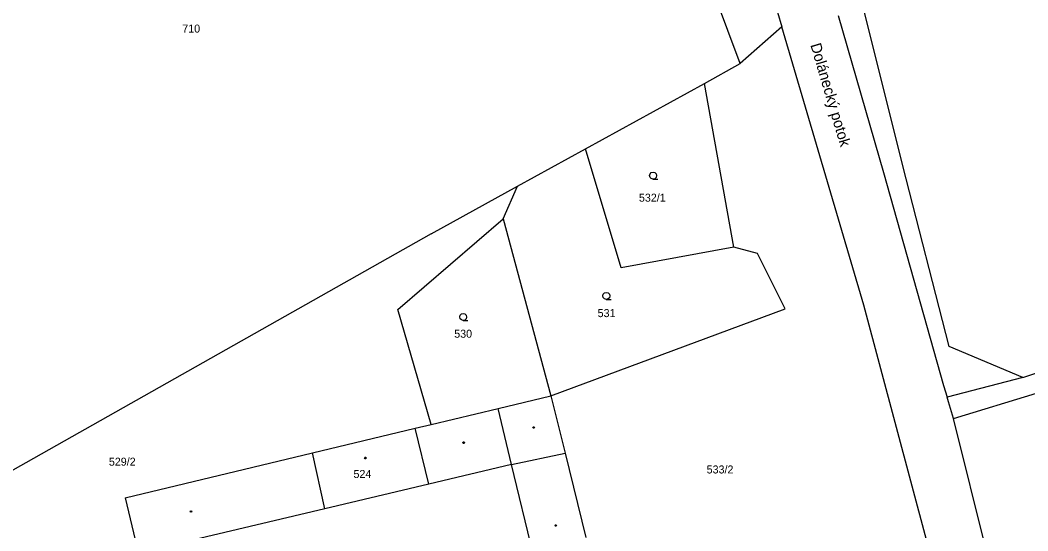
# Model space of a CAD drawing. Extents: x -812394 to -807601, y -1013097 to -1009266.
# Drawn here: x -809217.6 to -809003.5, y -1011595.7 to -1011487.2 of the extents above; entities that cross this region are included whole.
import ezdxf

# ---------------------------------------------------------------- set-up
doc = ezdxf.new("R2010")
doc.units = 0
for name, color, linetype in [('Default', 7, 'Continuous'), ('KN_HRANICE', 7, 'Continuous'), ('KN_KULTURY', 7, 'Continuous'), ('KN_PARCELY', 7, 'Continuous'), ('KN_SLUCKY', 7, 'Continuous')]:
    doc.layers.add(name, color=color, linetype=linetype)

# ---------------------------------------------------------------- blocks, each defined once
blk = doc.blocks.new('304')
at = {"layer": 'Default'}
blk.add_lwpolyline([(0, 0), (-0.38, 0.1), (-0.65, 0.37), (-0.75, 0.74), (-0.65, 1.11), (-0.38, 1.38), (-0.01, 1.48), (0.36, 1.38), (0.63, 1.11), (0.73, 0.73), (0.63, 0.35), (0.36, 0.08), (-0.02, -0.02), (0.98, -0.02)], dxfattribs=at)
blk = doc.blocks.new('402')
at = {"layer": 'Default'}
blk.add_lwpolyline([(0.09, 0.15), (0.18, 0), (0.09, -0.15), (-0.09, -0.15), (-0.18, 0), (-0.09, 0.15), (0.09, 0.15)], dxfattribs=at)

msp = doc.modelspace()

# ---------------------------------------------------------------- linework, layer by layer
at = {"layer": 'KN_HRANICE'}
for p, q in [((-809064.62, -1011496.45), (-809087.91, -1011433.54)), ((-809062.99, -1011464.38), (-809055.78, -1011488.65)), ((-809043.77, -1011486.23), (-809034.16, -1011519.56)), ((-809055.78, -1011488.65), (-809064.62, -1011496.45)), ((-809038.36, -1011547.76), (-809055.78, -1011488.65)), ((-809072.23, -1011500.64), (-809064.62, -1011496.45)), ((-809097.48, -1011514.55), (-809072.23, -1011500.64)), ((-809065.99, -1011535.45), (-809072.23, -1011500.64)), ((-809111.92, -1011522.51), (-809097.48, -1011514.55)), ((-809089.91, -1011539.85), (-809097.48, -1011514.55)), ((-809034.16, -1011519.56), (-809021.4, -1011564.8)), ((-809130.26, -1011532.62), (-809111.92, -1011522.51)), ((-809114.97, -1011529.38), (-809111.92, -1011522.51)), ((-809137.33, -1011548.69), (-809114.97, -1011529.38)), ((-809114.97, -1011529.38), (-809104.83, -1011566.99)), ((-809130.26, -1011532.62), (-809234.03, -1011591.15)), ((-809065.99, -1011535.45), (-809089.91, -1011539.85)), ((-809060.91, -1011536.79), (-809065.99, -1011535.45)), ((-809055.04, -1011548.54), (-809060.91, -1011536.79)), ((-809130.29, -1011573.09), (-809137.33, -1011548.69)), ((-809104.83, -1011566.99), (-809055.04, -1011548.54)), ((-809024.74, -1011598.61), (-809038.36, -1011547.76)), ((-809004.54, -1011563.13), (-808974.75, -1011553.11)), ((-809004.54, -1011563.13), (-809020.63, -1011567.3)), ((-809021.4, -1011564.8), (-809020.63, -1011567.3)), ((-809116.05, -1011569.68), (-809104.83, -1011566.99)), ((-809104.83, -1011566.99), (-809101.83, -1011579.14)), ((-809019.32, -1011571.78), (-809001.64, -1011566.41)), ((-809130.29, -1011573.09), (-809116.05, -1011569.68)), ((-809007.85, -1011617.52), (-809019.32, -1011571.78)), ((-809155.46, -1011579.11), (-809133.63, -1011573.89)), ((-809133.63, -1011573.89), (-809130.29, -1011573.09)), ((-809195.25, -1011588.63), (-809155.46, -1011579.11)), ((-809101.83, -1011579.14), (-809097.4, -1011597.08)), ((-809195.25, -1011588.63), (-809188.78, -1011615.82))]:
    msp.add_line(p, q, dxfattribs=at)
for points in [[(-809004.54, -1011563.13), (-809020.2, -1011556.5), (-809030.08, -1011518.19), (-809042.88, -1011466.74), (-809050.93, -1011432.87), (-809048.08, -1011401.48), (-809039.69, -1011388.93)], [(-809019.32, -1011571.78), (-809020.33, -1011568.3), (-809020.63, -1011567.3)]]:
    msp.add_lwpolyline(points, dxfattribs=at)
at = {"layer": 'KN_SLUCKY'}
for p, q in [((-809113.22, -1011581.56), (-809116.05, -1011569.68)), ((-809130.73, -1011585.72), (-809133.63, -1011573.89)), ((-809152.89, -1011590.98), (-809155.46, -1011579.11)), ((-809113.22, -1011581.56), (-809101.83, -1011579.14)), ((-809113.22, -1011581.56), (-809130.73, -1011585.72)), ((-809106.29, -1011609.87), (-809113.22, -1011581.56)), ((-809130.73, -1011585.72), (-809152.89, -1011590.98)), ((-809152.89, -1011590.98), (-809180.72, -1011597.59))]:
    msp.add_line(p, q, dxfattribs=at)

# ---------------------------------------------------------------- block references
at = {"layer": 'KN_KULTURY'}
for name, p in [('304', (-809083.12, -1011520.97)), ('304', (-809093.04, -1011546.51)), ('304', (-809123.46, -1011550.99)), ('402', (-809108.5, -1011573.72)), ('402', (-809123.35, -1011576.94)), ('402', (-809144.23, -1011580.19)), ('402', (-809181.3, -1011591.55)), ('402', (-809103.79, -1011594.52))]:
    msp.add_blockref(name, p, dxfattribs=at)

# ---------------------------------------------------------------- texts
at = {"layer": 'KN_PARCELY'}
for s, p in [('710', (-809183.14, -1011489.86)), ('532/1', (-809086.13, -1011525.77)), ('531', (-809094.9, -1011550.28)), ('530', (-809125.37, -1011554.66)), ('529/2', (-809198.74, -1011581.83)), ('524', (-809146.77, -1011584.44)), ('533/2', (-809071.74, -1011583.48))]:
    msp.add_text(s, height=1.7, dxfattribs=at).set_placement(p)
msp.add_text('Dolánecký potok', height=2.3, rotation=286.479, dxfattribs=at).set_placement((-809049.73, -1011492.48))

doc.saveas('drawing.dxf')
